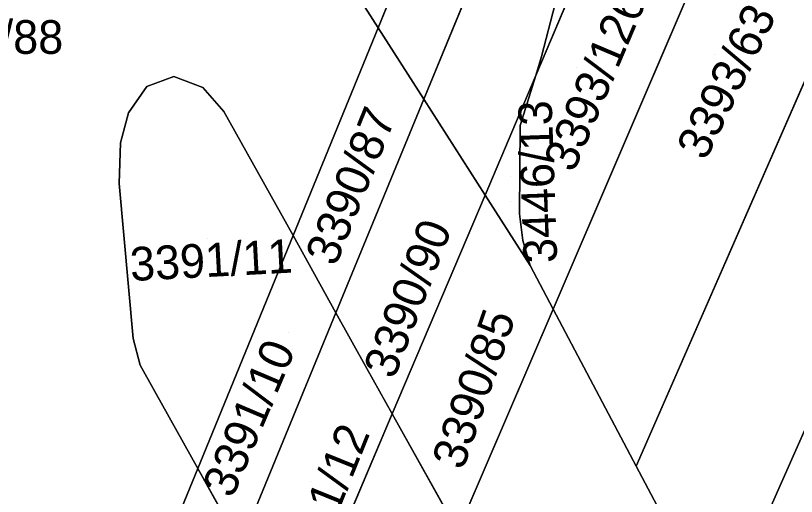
# Model space of a CAD drawing. Extents: x -262715 to -259381, y -1237238 to -1231182.
# Drawn here: x -261732.58 to -261686.19, y -1236267.66 to -1236239.11 of the extents above; entities that cross this region are included whole.
import ezdxf

# ---------------------------------------------------------------- set-up
doc = ezdxf.new("R2010")
doc.units = 0
for name, color, linetype in [('body_kn', 7, 'Continuous'), ('kladpar_druhypozemkov', 7, 'Continuous'), ('kladpar_hranice', 7, 'Continuous'), ('kladpar_parcelnecisla', 7, 'Continuous'), ('kladpar_plochy', 7, 'Continuous'), ('kladpar_sipky', 7, 'Continuous')]:
    doc.layers.add(name, color=color, linetype=linetype)

msp = doc.modelspace()

# ---------------------------------------------------------------- linework, layer by layer
at = {"layer": 'body_kn'}
for p, q in [((-261711.05, -1236239.83), (-261711.05, -1236239.83)), ((-261711.05, -1236239.83), (-261711.05, -1236239.83)), ((-261701.33, -1236241.54), (-261701.33, -1236241.54)), ((-261723.19, -1236242.73), (-261723.19, -1236242.73)), ((-261701.68, -1236242.67), (-261701.68, -1236242.67)), ((-261701.68, -1236242.67), (-261701.68, -1236242.67)), ((-261724.79, -1236243.32), (-261724.79, -1236243.32)), ((-261721.47, -1236243.37), (-261721.47, -1236243.37)), ((-261708.34, -1236244.08), (-261708.34, -1236244.08)), ((-261708.34, -1236244.08), (-261708.34, -1236244.08)), ((-261725.88, -1236244.88), (-261725.88, -1236244.88)), ((-261720.21, -1236244.8), (-261720.21, -1236244.8)), ((-261720.21, -1236244.8), (-261720.21, -1236244.8)), ((-261702.61, -1236245.64), (-261702.61, -1236245.64)), ((-261726.35, -1236246.66), (-261726.35, -1236246.66)), ((-261726.44, -1236249.08), (-261726.44, -1236249.08)), ((-261704.69, -1236249.77), (-261704.69, -1236249.77)), ((-261704.69, -1236249.77), (-261704.69, -1236249.77)), ((-261702.65, -1236250.88), (-261702.65, -1236250.88)), ((-261716.1, -1236252.17), (-261716.1, -1236252.17)), ((-261716.1, -1236252.17), (-261716.1, -1236252.17)), ((-261702.44, -1236252.47), (-261702.44, -1236252.47)), ((-261702.02, -1236253.95), (-261702.02, -1236253.95)), ((-261713.56, -1236256.75), (-261713.56, -1236256.75)), ((-261700.65, -1236256.54), (-261700.65, -1236256.54)), ((-261725.61, -1236258.28), (-261725.61, -1236258.28)), ((-261725.18, -1236259.86), (-261725.18, -1236259.86)), ((-261711.71, -1236260.06), (-261711.71, -1236260.06)), ((-261711.71, -1236260.06), (-261711.71, -1236260.06)), ((-261724.32, -1236261.43), (-261724.32, -1236261.43)), ((-261710.21, -1236262.75), (-261710.21, -1236262.75)), ((-261710.21, -1236262.75), (-261710.21, -1236262.75)), ((-261721.76, -1236266), (-261721.76, -1236266)), ((-261695.71, -1236265.87), (-261695.71, -1236265.87)), ((-261695.71, -1236265.87), (-261695.71, -1236265.87))]:
    msp.add_line(p, q, dxfattribs=at)
at = {"layer": 'kladpar_druhypozemkov'}
for p, q in [((-261691.06, -1236241.41), (-261691.06, -1236241.41)), ((-261699.27, -1236242.17), (-261699.27, -1236242.17)), ((-261703.18, -1236248.64), (-261703.18, -1236248.64)), ((-261713.8, -1236250.24), (-261713.8, -1236250.24)), ((-261721.2, -1236252.35), (-261721.2, -1236252.35)), ((-261709.24, -1236253.69), (-261709.24, -1236253.69)), ((-261716.4, -1236257.9), (-261716.4, -1236257.9)), ((-261705.7, -1236259.22), (-261705.7, -1236259.22)), ((-261715.05, -1236266.8), (-261715.05, -1236266.8))]:
    msp.add_line(p, q, dxfattribs=at)
at = {"layer": 'kladpar_hranice'}
for p, q in [((-261708.34, -1236244.08), (-261696.39, -1236215.08)), ((-261696.39, -1236215.08), (-261708.34, -1236244.08)), ((-261674.54, -1236217.48), (-261695.71, -1236265.87)), ((-261695.71, -1236265.87), (-261674.54, -1236217.48)), ((-261700.65, -1236256.54), (-261686.6, -1236223.78)), ((-261686.6, -1236223.78), (-261700.65, -1236256.54)), ((-261668.78, -1236225.55), (-261690.78, -1236275.18)), ((-261690.78, -1236275.18), (-261668.78, -1236225.55)), ((-261706.66, -1236229.12), (-261711.05, -1236239.83)), ((-261711.05, -1236239.83), (-261706.66, -1236229.12)), ((-261701.68, -1236242.67), (-261697.93, -1236233.84)), ((-261697.93, -1236233.84), (-261701.68, -1236242.67)), ((-261711.05, -1236239.83), (-261716.1, -1236252.17)), ((-261716.1, -1236252.17), (-261711.05, -1236239.83)), ((-261708.34, -1236244.08), (-261711.05, -1236239.83)), ((-261711.05, -1236239.83), (-261708.34, -1236244.08)), ((-261701.68, -1236242.67), (-261704.69, -1236249.77)), ((-261704.69, -1236249.77), (-261701.68, -1236242.67)), ((-261713.56, -1236256.75), (-261708.34, -1236244.08)), ((-261708.34, -1236244.08), (-261713.56, -1236256.75)), ((-261704.69, -1236249.77), (-261708.34, -1236244.08)), ((-261708.34, -1236244.08), (-261704.69, -1236249.77)), ((-261720.21, -1236244.8), (-261716.1, -1236252.17)), ((-261704.69, -1236249.77), (-261710.21, -1236262.75)), ((-261710.21, -1236262.75), (-261704.69, -1236249.77)), ((-261716.1, -1236252.17), (-261721.76, -1236266)), ((-261721.76, -1236266), (-261716.1, -1236252.17)), ((-261716.1, -1236252.17), (-261713.56, -1236256.75)), ((-261713.56, -1236256.75), (-261716.1, -1236252.17)), ((-261719.23, -1236270.53), (-261713.56, -1236256.75)), ((-261713.56, -1236256.75), (-261719.23, -1236270.53)), ((-261713.56, -1236256.75), (-261711.71, -1236260.06)), ((-261700.65, -1236256.54), (-261706.31, -1236269.73)), ((-261706.31, -1236269.73), (-261700.65, -1236256.54)), ((-261695.71, -1236265.87), (-261700.65, -1236256.54)), ((-261711.71, -1236260.06), (-261710.21, -1236262.75)), ((-261710.21, -1236262.75), (-261715.98, -1236276.36)), ((-261715.98, -1236276.36), (-261710.21, -1236262.75)), ((-261710.21, -1236262.75), (-261706.31, -1236269.73)), ((-261706.31, -1236269.73), (-261710.21, -1236262.75)), ((-261721.76, -1236266), (-261727.04, -1236278.88)), ((-261727.04, -1236278.88), (-261721.76, -1236266)), ((-261719.23, -1236270.53), (-261721.76, -1236266)), ((-261721.76, -1236266), (-261719.23, -1236270.53))]:
    msp.add_line(p, q, dxfattribs=at)
for points in [[(-261736.6, -1236199.28), (-261733.44, -1236204.89), (-261730.82, -1236208.93), (-261711.05, -1236239.83)], [(-261711.05, -1236239.83), (-261730.82, -1236208.93), (-261729.14, -1236211.14), (-261727.09, -1236213.24), (-261724.8, -1236214.96), (-261722.32, -1236216.58), (-261719.04, -1236217.82), (-261711.31, -1236219.82), (-261708.62, -1236219.84), (-261705.85, -1236219.4), (-261703.53, -1236218.72), (-261702.15, -1236218.1)], [(-261697.93, -1236233.84), (-261698.03, -1236233.95), (-261699.36, -1236236.13), (-261700.52, -1236238.41), (-261701.33, -1236241.54), (-261701.68, -1236242.67)], [(-261701.68, -1236242.67), (-261701.33, -1236241.54), (-261700.52, -1236238.41), (-261699.36, -1236236.13), (-261698.03, -1236233.95)], [(-261721.76, -1236266), (-261724.32, -1236261.43), (-261725.18, -1236259.86), (-261725.61, -1236258.28), (-261726.44, -1236249.08), (-261726.35, -1236246.66), (-261725.88, -1236244.88), (-261724.79, -1236243.32), (-261723.19, -1236242.73), (-261721.47, -1236243.37), (-261720.21, -1236244.8)], [(-261716.1, -1236252.17), (-261720.21, -1236244.8), (-261721.47, -1236243.37), (-261723.19, -1236242.73), (-261724.79, -1236243.32), (-261725.88, -1236244.88), (-261726.35, -1236246.66), (-261726.44, -1236249.08), (-261725.61, -1236258.28), (-261725.18, -1236259.86), (-261724.32, -1236261.43), (-261721.76, -1236266)], [(-261701.68, -1236242.67), (-261702.61, -1236245.64), (-261702.65, -1236250.88), (-261702.44, -1236252.47), (-261702.02, -1236253.95), (-261704.69, -1236249.77)], [(-261700.65, -1236256.54), (-261702.02, -1236253.95), (-261702.44, -1236252.47), (-261702.65, -1236250.88), (-261702.61, -1236245.64), (-261701.68, -1236242.67)], [(-261704.69, -1236249.77), (-261702.02, -1236253.95), (-261700.65, -1236256.54)], [(-261710.21, -1236262.75), (-261711.71, -1236260.06), (-261713.56, -1236256.75)], [(-261700.65, -1236256.54), (-261695.71, -1236265.87), (-261690.88, -1236274.99), (-261690.78, -1236275.18), (-261685.79, -1236284.68), (-261682.11, -1236291.68), (-261680.96, -1236294.05), (-261678.58, -1236298.94), (-261674.41, -1236307.53), (-261669.93, -1236316.75), (-261669.56, -1236317.51), (-261664.03, -1236328.88), (-261656.52, -1236343.65), (-261643.39, -1236367.05), (-261642.58, -1236368.52), (-261637.27, -1236378.15), (-261632.39, -1236387), (-261631.95, -1236387.8), (-261627.36, -1236396.11), (-261610.66, -1236426.41), (-261595.94, -1236462.59), (-261586.92, -1236502.02), (-261585.57, -1236521.6)], [(-261690.78, -1236275.18), (-261690.88, -1236274.99), (-261695.71, -1236265.87)]]:
    msp.add_lwpolyline(points, dxfattribs=at)
at = {"layer": 'kladpar_plochy'}
for p, q in [((-261706.31, -1236269.73), (-261700.65, -1236256.54)), ((-261700.65, -1236256.54), (-261695.71, -1236265.87)), ((-261695.71, -1236265.87), (-261690.88, -1236274.99))]:
    msp.add_line(p, q, dxfattribs=at)
msp.add_lwpolyline([(-261733.44, -1236204.89), (-261730.82, -1236208.93), (-261711.05, -1236239.83), (-261716.1, -1236252.17), (-261720.21, -1236244.8), (-261721.47, -1236243.37), (-261723.19, -1236242.73), (-261724.79, -1236243.32), (-261725.88, -1236244.88), (-261726.35, -1236246.66), (-261726.44, -1236249.08), (-261725.61, -1236258.28), (-261725.18, -1236259.86), (-261724.32, -1236261.43), (-261721.76, -1236266), (-261727.04, -1236278.88), (-261732.83, -1236268.65)], dxfattribs=at)
for points in [[(-261708.12, -1236229.95), (-261706.66, -1236229.12), (-261711.05, -1236239.83), (-261730.82, -1236208.93), (-261729.14, -1236211.14), (-261727.09, -1236213.24), (-261724.8, -1236214.96), (-261722.32, -1236216.58), (-261719.04, -1236217.82), (-261711.31, -1236219.82), (-261708.62, -1236219.84), (-261705.85, -1236219.4), (-261703.53, -1236218.72), (-261702.15, -1236218.1), (-261705.75, -1236226.88), (-261708.82, -1236228.29)], [(-261696.39, -1236215.08), (-261687.98, -1236210.38), (-261697.93, -1236233.84), (-261698.03, -1236233.95), (-261699.36, -1236236.13), (-261700.52, -1236238.41), (-261701.33, -1236241.54), (-261701.68, -1236242.67), (-261704.69, -1236249.77), (-261708.34, -1236244.08)], [(-261706.66, -1236229.12), (-261702.34, -1236226.65), (-261701.95, -1236225.78), (-261702.92, -1236225.58), (-261705.75, -1236226.88), (-261702.15, -1236218.1), (-261700.39, -1236217.31), (-261696.39, -1236215.08), (-261708.34, -1236244.08), (-261711.05, -1236239.83)], [(-261686.6, -1236223.78), (-261682.18, -1236220.45), (-261675.95, -1236216.71), (-261674.54, -1236217.48), (-261695.71, -1236265.87), (-261700.65, -1236256.54)], [(-261674.54, -1236217.48), (-261672.71, -1236218.49), (-261668.78, -1236225.55), (-261690.78, -1236275.18), (-261690.88, -1236274.99), (-261695.71, -1236265.87)], [(-261686.6, -1236223.78), (-261700.65, -1236256.54), (-261702.02, -1236253.95), (-261702.44, -1236252.47), (-261702.65, -1236250.88), (-261702.61, -1236245.64), (-261701.68, -1236242.67), (-261697.93, -1236233.84), (-261696.25, -1236231.88), (-261694.66, -1236229.73), (-261690.56, -1236226.76)], [(-261668.78, -1236225.55), (-261664.21, -1236233.74), (-261663.33, -1236235.25), (-261667.83, -1236245.14), (-261670.25, -1236246.52), (-261669.25, -1236248.27), (-261675.6, -1236262.26), (-261685.79, -1236284.68), (-261690.78, -1236275.18)], [(-261698.03, -1236233.95), (-261697.93, -1236233.84), (-261701.68, -1236242.67), (-261701.33, -1236241.54), (-261700.52, -1236238.41), (-261699.36, -1236236.13)], [(-261711.05, -1236239.83), (-261708.34, -1236244.08), (-261713.56, -1236256.75), (-261716.1, -1236252.17)], [(-261720.21, -1236244.8), (-261716.1, -1236252.17), (-261721.76, -1236266), (-261724.32, -1236261.43), (-261725.18, -1236259.86), (-261725.61, -1236258.28), (-261726.44, -1236249.08), (-261726.35, -1236246.66), (-261725.88, -1236244.88), (-261724.79, -1236243.32), (-261723.19, -1236242.73), (-261721.47, -1236243.37)], [(-261701.68, -1236242.67), (-261702.61, -1236245.64), (-261702.65, -1236250.88), (-261702.44, -1236252.47), (-261702.02, -1236253.95), (-261704.69, -1236249.77)], [(-261708.34, -1236244.08), (-261704.69, -1236249.77), (-261710.21, -1236262.75), (-261711.71, -1236260.06), (-261713.56, -1236256.75)], [(-261704.69, -1236249.77), (-261702.02, -1236253.95), (-261700.65, -1236256.54), (-261706.31, -1236269.73), (-261710.21, -1236262.75)], [(-261716.1, -1236252.17), (-261713.56, -1236256.75), (-261719.23, -1236270.53), (-261721.76, -1236266)], [(-261711.71, -1236260.06), (-261710.21, -1236262.75), (-261715.98, -1236276.36), (-261719.23, -1236270.53), (-261713.56, -1236256.75)], [(-261710.21, -1236262.75), (-261706.31, -1236269.73), (-261712.11, -1236283.27), (-261715.98, -1236276.36)], [(-261724.51, -1236283.35), (-261727.04, -1236278.88), (-261721.76, -1236266), (-261719.23, -1236270.53)]]:
    msp.add_lwpolyline(points, close=True, dxfattribs=at)
at = {"layer": 'kladpar_sipky'}
msp.add_line((-261703.2, -1236250.13), (-261703.2, -1236250.13), dxfattribs=at)

# ---------------------------------------------------------------- texts
at = {"layer": 'kladpar_parcelnecisla'}
for s, rotation, p in [('3393/126', 67, (-261699.432, -1236248.494)), ('3393/63', 64, (-261691.592, -1236247.784)), ('3446/13', 92, (-261700.4, -1236253.778)), ('3390/87', 68, (-261713.576, -1236254.068)), ('3390/90', 69, (-261710.101, -1236260.763)), ('3391/11', 3, (-261725.739, -1236254.871)), ('3390/85', 71, (-261706.003, -1236266.153)), ('3391/10', 67, (-261719.704, -1236267.835)), ('3389/10', 297, (-261738.347, -1236263.936)), ('3391/12', 68, (-261715.126, -1236272.874))]:
    msp.add_text(s, height=2, rotation=rotation, dxfattribs=at).set_placement(p)
msp.add_text('3390/88', height=2, dxfattribs=at).set_placement((-261739.422, -1236241.38))

doc.saveas('drawing.dxf')
